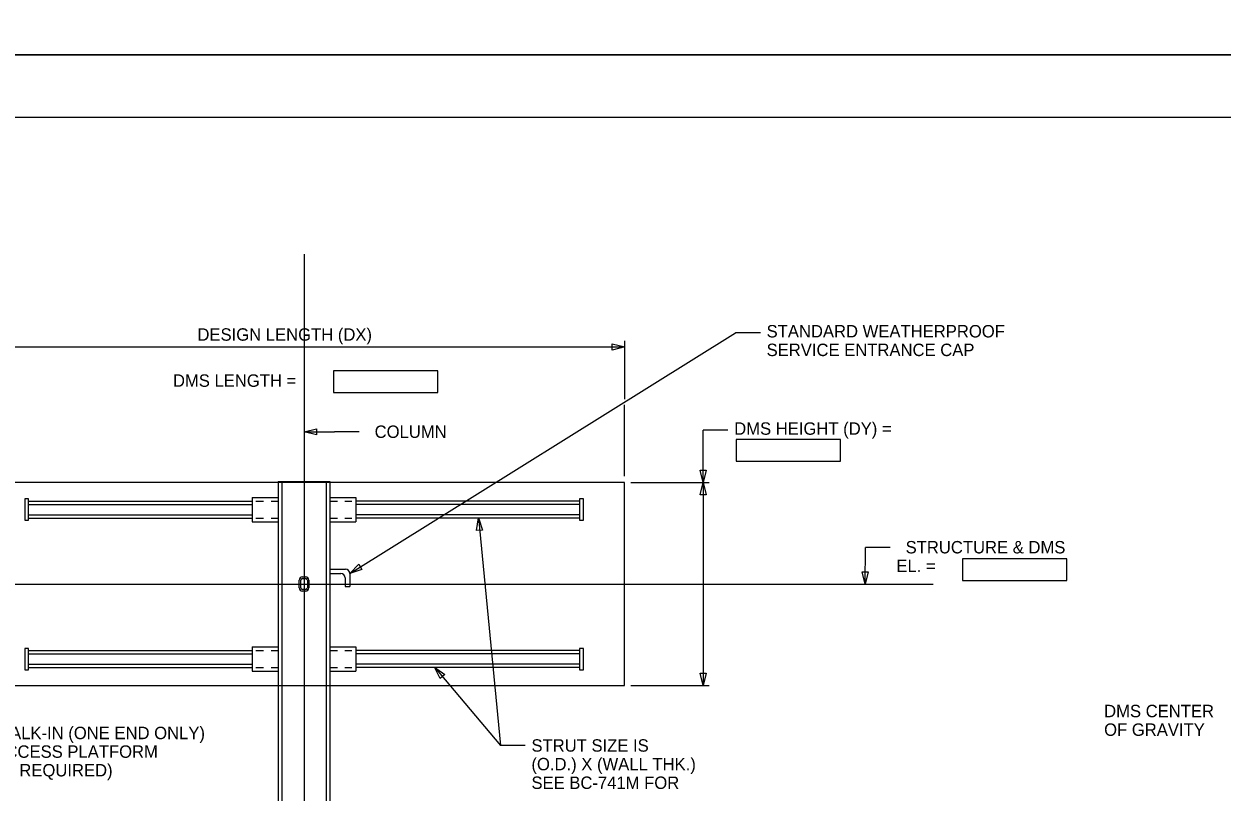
# Model space of a CAD drawing. Extents: x 3829340 to 3831660, y 499389 to 501171.
# Drawn here: x 3829492.7 to 3829781.8, y 499805.2 to 499990.7 of the extents above; entities that cross this region are included whole.
import ezdxf

# ---------------------------------------------------------------- set-up
doc = ezdxf.new("R2010")
doc.units = 0
for name, color, linetype in [('2', 7, 'Continuous'), ('CNTR', 7, 'Continuous'), ('DIM TXT', 7, 'Continuous'), ('PLT-BNDY', 7, 'Continuous'), ('sign', 7, 'Continuous'), ('structure', 7, 'Continuous')]:
    doc.layers.add(name, color=color, linetype=linetype)

msp = doc.modelspace()

# ---------------------------------------------------------------- linework, layer by layer
at = {"layer": '2'}
msp.add_line((3829379.96, 499968.19), (3830165.96, 499968.19), dxfattribs=at)
at = {"layer": 'CNTR'}
for p, q in [((3829560.27, 499935.08), (3829560.27, 499674.93)), ((3829427.35, 499855.45), (3829712.05, 499855.45))]:
    msp.add_line(p, q, dxfattribs=at)
at = {"layer": 'DIM TXT'}
for p, q in [((3829571.31, 499858), (3829664.39, 499916.1)), ((3829670.39, 499916.1), (3829664.39, 499916.1)), ((3829482.91, 499912.7), (3829637.64, 499912.7)), ((3829637.64, 499900.12), (3829637.64, 499914.2)), ((3829637.63, 499881.46), (3829637.63, 499898.7)), ((3829560.27, 499892.2), (3829567.59, 499892.17)), ((3829573.59, 499892.17), (3829567.59, 499892.17)), ((3829656.57, 499879.96), (3829656.58, 499892.6)), ((3829662.57, 499892.6), (3829656.58, 499892.6)), ((3829639.13, 499879.96), (3829658.07, 499879.96)), ((3829656.57, 499879.96), (3829656.57, 499830.94)), ((3829602.34, 499871.41), (3829607.64, 499816.47)), ((3829695.68, 499855.42), (3829695.72, 499864.28)), ((3829701.71, 499864.28), (3829695.72, 499864.28)), ((3829591.72, 499835.41), (3829607.64, 499816.47)), ((3829639.13, 499830.94), (3829658.07, 499830.94)), ((3829613.64, 499816.47), (3829607.64, 499816.47)), ((3829613.64, 499816.47), (3829607.64, 499816.47))]:
    msp.add_line(p, q, dxfattribs=at)
for points in [[(3829634.64, 499913.45), (3829637.64, 499912.7), (3829634.64, 499911.95)], [(3829567.35, 499901.69), (3829592.55, 499901.69), (3829592.55, 499906.94), (3829567.35, 499906.94)], [(3829563.27, 499891.44), (3829560.27, 499892.2), (3829563.28, 499892.94)], [(3829664.51, 499885.09), (3829689.7, 499885.09), (3829689.7, 499890.34), (3829664.51, 499890.34)], [(3829657.32, 499882.96), (3829656.57, 499879.96), (3829655.82, 499882.96)], [(3829655.82, 499876.96), (3829656.57, 499879.96), (3829657.32, 499876.96)], [(3829601.88, 499868.35), (3829602.34, 499871.41), (3829603.37, 499868.49)], [(3829574.25, 499858.96), (3829571.31, 499858), (3829573.46, 499860.23)], [(3829719.17, 499856.27), (3829744.36, 499856.27), (3829744.36, 499861.52), (3829719.17, 499861.52)], [(3829696.44, 499858.42), (3829695.68, 499855.42), (3829694.94, 499858.42)], [(3829593.08, 499832.63), (3829591.72, 499835.41), (3829594.22, 499833.59)], [(3829657.32, 499833.94), (3829656.57, 499830.94), (3829655.82, 499833.94)]]:
    msp.add_lwpolyline(points, close=True, dxfattribs=at)
at = {"layer": 'PLT-BNDY'}
for points in [[(3829339.96, 500577.19), (3830180.96, 500577.19), (3830180.96, 499983.19), (3829339.96, 499983.19)], [(3829339.96, 499983.19), (3830180.96, 499983.19), (3830180.96, 499389.19), (3829339.96, 499389.19)]]:
    msp.add_lwpolyline(points, close=True, dxfattribs=at)
at = {"layer": 'sign'}
for p, q in [((3829637.63, 499879.96), (3829482.91, 499879.96)), ((3829637.63, 499877.21), (3829637.63, 499879.96)), ((3829637.63, 499833.5), (3829637.63, 499877.21)), ((3829482.91, 499830.94), (3829637.63, 499830.94)), ((3829637.63, 499830.94), (3829637.63, 499833.5))]:
    msp.add_line(p, q, dxfattribs=at)
at = {"layer": 'structure'}
for p, q in [((3829554.02, 499880.19), (3829566.52, 499880.19)), ((3829554.02, 499880.19), (3829554.02, 499855.45)), ((3829554.92, 499880.19), (3829554.92, 499715.35)), ((3829565.62, 499880.19), (3829565.62, 499715.35)), ((3829566.52, 499880.19), (3829566.52, 499746.82)), ((3829492.87, 499876), (3829492.87, 499870.85)), ((3829493.8, 499876), (3829492.87, 499876)), ((3829493.8, 499870.85), (3829493.8, 499876)), ((3829493.8, 499875.49), (3829547.77, 499875.49)), ((3829493.8, 499874.68), (3829547.77, 499874.68)), ((3829547.77, 499876.38), (3829547.77, 499870.46)), ((3829547.77, 499876.38), (3829554.02, 499876.38)), ((3829548.65, 499875.49), (3829550.48, 499875.49)), ((3829552.35, 499875.49), (3829554.02, 499875.49)), ((3829566.52, 499876.38), (3829572.77, 499876.38)), ((3829566.52, 499875.49), (3829568.3, 499875.49)), ((3829570.11, 499875.49), (3829571.82, 499875.49)), ((3829572.77, 499876.38), (3829572.77, 499870.46)), ((3829626.74, 499875.49), (3829572.77, 499875.49)), ((3829626.74, 499874.68), (3829572.77, 499874.68)), ((3829626.74, 499876), (3829626.74, 499870.85)), ((3829627.67, 499876), (3829626.74, 499876)), ((3829627.67, 499870.85), (3829627.67, 499876)), ((3829493.8, 499872.16), (3829547.77, 499872.16)), ((3829493.8, 499871.36), (3829547.77, 499871.36)), ((3829548.65, 499871.36), (3829550.48, 499871.36)), ((3829552.35, 499871.36), (3829554.02, 499871.36)), ((3829566.52, 499871.36), (3829568.3, 499871.36)), ((3829570.11, 499871.36), (3829571.82, 499871.36)), ((3829626.74, 499872.16), (3829572.77, 499872.16)), ((3829626.74, 499871.36), (3829572.77, 499871.36)), ((3829492.87, 499870.85), (3829493.8, 499870.85)), ((3829547.77, 499870.46), (3829554.02, 499870.46)), ((3829566.52, 499870.46), (3829572.77, 499870.46)), ((3829626.74, 499870.85), (3829627.67, 499870.85)), ((3829559.88, 499857.15), (3829560.66, 499857.15)), ((3829566.57, 499859.04), (3829570.28, 499859.04)), ((3829566.57, 499858), (3829569.18, 499858)), ((3829570.19, 499856.97), (3829570.19, 499854.84)), ((3829571.31, 499858), (3829571.31, 499854.84)), ((3829554.02, 499855.45), (3829554.02, 499746.78)), ((3829559.1, 499854.54), (3829559.1, 499856.37)), ((3829559.49, 499854.54), (3829559.49, 499856.37)), ((3829559.88, 499856.76), (3829560.66, 499856.76)), ((3829560.66, 499854.15), (3829559.88, 499854.15)), ((3829561.06, 499856.37), (3829561.06, 499854.54)), ((3829561.45, 499856.37), (3829561.45, 499854.54)), ((3829570.19, 499854.84), (3829571.31, 499854.84)), ((3829560.66, 499853.76), (3829559.88, 499853.76)), ((3829492.87, 499839.91), (3829492.87, 499834.76)), ((3829493.8, 499839.91), (3829492.87, 499839.91)), ((3829493.8, 499834.76), (3829493.8, 499839.91)), ((3829547.77, 499840.29), (3829547.77, 499834.38)), ((3829547.77, 499840.29), (3829554.02, 499840.29)), ((3829566.52, 499840.29), (3829572.77, 499840.29)), ((3829572.77, 499840.29), (3829572.77, 499834.38)), ((3829626.74, 499839.91), (3829626.74, 499834.76)), ((3829627.67, 499839.91), (3829626.74, 499839.91)), ((3829627.67, 499834.76), (3829627.67, 499839.91)), ((3829493.8, 499839.4), (3829547.77, 499839.4)), ((3829493.8, 499838.6), (3829547.77, 499838.6)), ((3829548.65, 499839.4), (3829550.48, 499839.4)), ((3829552.35, 499839.4), (3829554.02, 499839.4)), ((3829566.52, 499839.4), (3829568.3, 499839.4)), ((3829570.11, 499839.4), (3829571.82, 499839.4)), ((3829626.74, 499839.4), (3829572.77, 499839.4)), ((3829626.74, 499838.6), (3829572.77, 499838.6)), ((3829492.87, 499834.76), (3829493.8, 499834.76)), ((3829493.8, 499836.07), (3829547.77, 499836.07)), ((3829493.8, 499835.27), (3829547.77, 499835.27)), ((3829547.77, 499834.38), (3829554.02, 499834.38)), ((3829548.65, 499835.27), (3829550.48, 499835.27)), ((3829552.35, 499835.27), (3829554.02, 499835.27)), ((3829566.52, 499835.27), (3829568.3, 499835.27)), ((3829566.52, 499834.38), (3829572.77, 499834.38)), ((3829570.11, 499835.27), (3829571.82, 499835.27)), ((3829626.74, 499836.07), (3829572.77, 499836.07)), ((3829626.74, 499835.27), (3829572.77, 499835.27)), ((3829626.74, 499834.76), (3829627.67, 499834.76))]:
    msp.add_line(p, q, dxfattribs=at)
for centre, radius, start, end in [((3829559.88, 499856.37), 0.781, 90, 180), ((3829560.66, 499856.37), 0.781, 0, 90), ((3829569.15, 499856.96), 1.04, 0, 90), ((3829570.27, 499858), 1.04, 0, 90), ((3829559.88, 499854.54), 0.781, 180, 270), ((3829559.88, 499856.37), 0.391, 90, 180), ((3829559.88, 499854.54), 0.391, 180, 270), ((3829560.66, 499856.37), 0.391, 0, 90), ((3829560.66, 499854.54), 0.781, 270, 0), ((3829560.66, 499854.54), 0.391, 270, 0)]:
    msp.add_arc(centre, radius, start, end, dxfattribs=at)

# ---------------------------------------------------------------- texts
at = {"layer": 'DIM TXT'}
for s, height, p in [('STANDARD WEATHERPROOF', 2.9999, (3829671.89, 499914.99)), ('DESIGN LENGTH (DX)', 2.9999, (3829534.54, 499914.2)), ('SERVICE ENTRANCE CAP', 2.9999, (3829671.89, 499910.49)), ('DMS LENGTH =', 2.9999, (3829528.63, 499903.07)), ('DMS HEIGHT (DY) =', 2.9999, (3829664.07, 499891.49)), ('  COLUMN', 3, (3829575.07, 499890.73)), ('  STRUCTURE & DMS', 2.9999, (3829703.21, 499862.84)), ('EL. =', 3, (3829703.21, 499858.34)), ('DMS CENTER', 3, (3829753.34, 499823.29)), ('WALK-IN (ONE END ONLY)', 2.9999, (3829485.54, 499817.99)), ('OF GRAVITY', 3, (3829753.34, 499818.79)), ('ACCESS PLATFORM', 2.9999, (3829485.54, 499813.49)), ('STRUT SIZE IS', 2.9999, (3829615.14, 499814.97)), ('(O.D.) X (WALL THK.)', 2.9999, (3829615.14, 499810.47)), ('(IF REQUIRED)', 2.9999, (3829485.54, 499808.99)), ('SEE BC-741M FOR', 2.9999, (3829615.14, 499805.97))]:
    msp.add_text(s, height=height, dxfattribs=at).set_placement(p)

doc.saveas('drawing.dxf')
